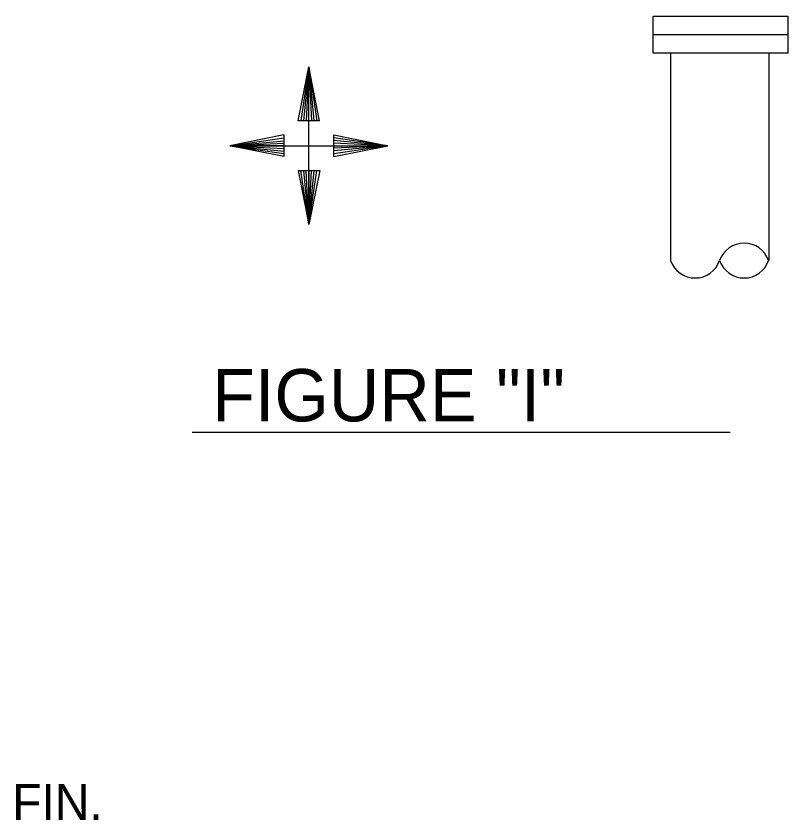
# Model space of a CAD drawing. Extents: x 10040.55 to 10045.84, y 10033.26 to 10035.76.
# Drawn here: x 10041.2964 to 10041.5115, y 10033.9686 to 10034.1926 of the extents above; entities that cross this region are included whole.
import ezdxf

# ---------------------------------------------------------------- set-up
doc = ezdxf.new("R2010")
doc.units = 0
doc.layers.add('Level 2', color=7, linetype='Continuous')

msp = doc.modelspace()

# ---------------------------------------------------------------- linework, layer by layer
at = {"layer": 'Level 2'}
for p, q in [((10041.47397, 10034.1875), (10041.51152, 10034.1875)), ((10041.47881, 10034.18229), (10041.47881, 10034.12452)), ((10041.50616, 10034.18229), (10041.50616, 10034.12452)), ((10041.37501, 10034.16348), (10041.37803, 10034.17852)), ((10041.37803, 10034.17852), (10041.37582, 10034.16347)), ((10041.37803, 10034.17852), (10041.37655, 10034.16346)), ((10041.37803, 10034.17852), (10041.37729, 10034.16347)), ((10041.37803, 10034.13453), (10041.37803, 10034.17852)), ((10041.37805, 10034.16346), (10041.37803, 10034.17852)), ((10041.38103, 10034.16347), (10041.37803, 10034.17852)), ((10041.37803, 10034.17852), (10041.37943, 10034.16345)), ((10041.37803, 10034.17852), (10041.37875, 10034.16347)), ((10041.37803, 10034.17852), (10041.38027, 10034.16347)), ((10041.38103, 10034.16347), (10041.37501, 10034.16348)), ((10041.37109, 10034.15952), (10041.35604, 10034.15652)), ((10041.35604, 10034.15652), (10041.37109, 10034.15876)), ((10041.37109, 10034.15952), (10041.37108, 10034.1535)), ((10041.38498, 10034.15352), (10041.38499, 10034.15954)), ((10041.40003, 10034.15652), (10041.38498, 10034.15873)), ((10041.38499, 10034.15954), (10041.40003, 10034.15652)), ((10041.35604, 10034.15652), (10041.37111, 10034.15792)), ((10041.35604, 10034.15652), (10041.37109, 10034.15724)), ((10041.3711, 10034.15654), (10041.35604, 10034.15652)), ((10041.35604, 10034.15652), (10041.40003, 10034.15652)), ((10041.37108, 10034.1535), (10041.35604, 10034.15652)), ((10041.35604, 10034.15652), (10041.3711, 10034.15504)), ((10041.35604, 10034.15652), (10041.37109, 10034.15431)), ((10041.35604, 10034.15652), (10041.37109, 10034.15578)), ((10041.40003, 10034.15652), (10041.38496, 10034.15513)), ((10041.40003, 10034.15652), (10041.38497, 10034.158)), ((10041.38497, 10034.1565), (10041.40003, 10034.15652)), ((10041.40003, 10034.15652), (10041.38498, 10034.15726)), ((10041.38498, 10034.15352), (10041.40003, 10034.15652)), ((10041.40003, 10034.15652), (10041.38498, 10034.1558)), ((10041.40003, 10034.15652), (10041.38498, 10034.15428)), ((10041.37503, 10034.14958), (10041.38105, 10034.14957)), ((10041.37503, 10034.14958), (10041.37803, 10034.13453)), ((10041.37803, 10034.13453), (10041.37579, 10034.14958)), ((10041.37803, 10034.13453), (10041.37664, 10034.1496)), ((10041.37803, 10034.13453), (10041.37731, 10034.14958)), ((10041.37801, 10034.14959), (10041.37803, 10034.13453)), ((10041.37803, 10034.13453), (10041.37951, 10034.14959)), ((10041.37803, 10034.13453), (10041.38024, 10034.14958)), ((10041.37803, 10034.13453), (10041.37877, 10034.14958)), ((10041.38105, 10034.14957), (10041.37803, 10034.13453)), ((10041.34551, 10034.07667), (10041.49544, 10034.07667))]:
    msp.add_line(p, q, dxfattribs=at)
msp.add_lwpolyline([(10041.51152, 10034.18229), (10041.47397, 10034.18229), (10041.47397, 10034.19265), (10041.51152, 10034.19265)], close=True, dxfattribs=at)
for centre, start, end in [((10041.49931, 10034.12216), 19.0959, 160.9048), ((10041.48565, 10034.12689), 199.0959, 340.9048), ((10041.49931, 10034.12689), 199.0952, 340.9041)]:
    msp.add_arc(centre, 0.00723, start, end, dxfattribs=at)

# ---------------------------------------------------------------- texts
for s, height, p in [('FIGURE "I"', 0.014583, (10041.35108, 10034.0797)), ('FIN. ', 0.01, (10041.29534, 10033.96865))]:
    msp.add_text(s, height=height, dxfattribs=at).set_placement(p)

doc.saveas('drawing.dxf')
